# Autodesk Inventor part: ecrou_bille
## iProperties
Shininess: 20.0
Length Units: 11269
Angle Units: 11279
Time Units: 11290
Mass Units: 11283
Length Display Precision: 3
Angle Display Precision: 2
Created: 2004-05
Part Number: ecrou_bille
Material: Par défaut
Document SubType Name: Modélisation
Designer: Danielc
Density: 0.0
Volumn: 0.0
Area: 0.0
PropertySet Name: Model Information
Control State: 0
Master: False
Checked Out: False
Author: Danielc
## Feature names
1. Révolution1 [Revolution]
2. Chanfrein1 [Chamfer]
3. Chanfrein2 [Chamfer]
4. Chanfrein3 [Chamfer]
5. Chanfrein4 [Chamfer]
6. Chanfrein5 [Chamfer]
